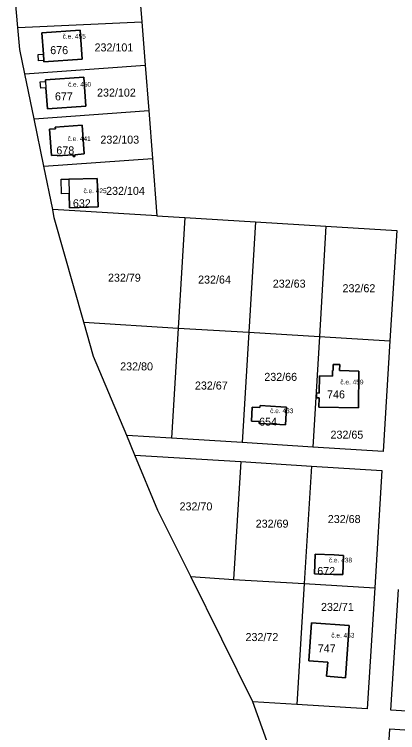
# Model space of a CAD drawing. Extents: x -887272 to -880188, y -1026687 to -1021896.
# Drawn here: x -882003.9 to -881922.6, y -1023755.1 to -1023602.5 of the extents above; entities that cross this region are included whole.
import ezdxf

# ---------------------------------------------------------------- set-up
doc = ezdxf.new("R2010")
doc.units = 0
for name, color, linetype in [('Definiční body', 7, 'Continuous'), ('Hranice parcel', 7, 'Continuous'), ('Parcelní čísla', 7, 'Continuous'), ('Polygon budovy', 7, 'Continuous'), ('Vnitřní kresba', 7, 'Continuous')]:
    doc.layers.add(name, color=color, linetype=linetype)

msp = doc.modelspace()

# ---------------------------------------------------------------- linework, layer by layer
at = {"layer": 'Hranice parcel'}
for p, q in [((-881977.56, -1023595.07), (-881976.82, -1023604.15)), ((-882003.11, -1023605.34), (-882003.86, -1023596.94)), ((-882003.11, -1023605.34), (-881976.82, -1023604.15)), ((-881976.82, -1023604.15), (-881976.12, -1023613.34)), ((-882001.64, -1023615.16), (-881976.12, -1023613.34)), ((-881976.12, -1023613.34), (-881975.38, -1023622.97)), ((-881999.69, -1023624.69), (-882001.64, -1023615.16)), ((-881999.69, -1023624.69), (-881975.38, -1023622.97)), ((-881975.38, -1023622.97), (-881974.6, -1023633.13)), ((-881997.63, -1023634.76), (-881999.69, -1023624.69)), ((-881997.63, -1023634.76), (-881974.6, -1023633.13)), ((-881974.6, -1023633.13), (-881973.66, -1023645.33)), ((-881995.74, -1023643.96), (-881997.63, -1023634.76)), ((-881973.66, -1023645.33), (-881995.74, -1023643.96)), ((-881973.66, -1023645.33), (-881967.74, -1023645.7)), ((-881967.74, -1023645.7), (-881969.15, -1023669.15)), ((-881967.74, -1023645.7), (-881952.7, -1023646.62)), ((-881952.7, -1023646.62), (-881954.14, -1023670.06)), ((-881952.7, -1023646.62), (-881937.78, -1023647.52)), ((-881937.78, -1023647.52), (-881939.18, -1023670.97)), ((-881989.11, -1023667.93), (-881969.15, -1023669.15)), ((-881969.15, -1023669.15), (-881970.55, -1023692.51)), ((-881969.15, -1023669.15), (-881954.14, -1023670.06)), ((-881954.14, -1023670.06), (-881955.58, -1023693.49)), ((-881954.14, -1023670.06), (-881939.18, -1023670.97)), ((-881939.18, -1023670.97), (-881940.59, -1023694.43)), ((-881939.18, -1023670.97), (-881924.21, -1023671.89)), ((-881970.55, -1023692.51), (-881980.01, -1023691.98)), ((-881978.29, -1023696.16), (-881980.01, -1023691.98)), ((-881955.58, -1023693.49), (-881970.55, -1023692.51)), ((-881940.59, -1023694.43), (-881955.58, -1023693.49)), ((-881978.29, -1023696.16), (-881955.81, -1023697.47)), ((-881955.81, -1023697.47), (-881957.38, -1023722.54)), ((-881955.81, -1023697.47), (-881940.88, -1023698.48)), ((-881940.88, -1023698.48), (-881942.4, -1023723.43)), ((-881953.3, -1023748.53), (-881966.43, -1023721.93)), ((-881966.43, -1023721.93), (-881957.38, -1023722.54)), ((-881957.38, -1023722.54), (-881942.4, -1023723.43)), ((-881942.4, -1023723.43), (-881943.98, -1023749.08)), ((-881942.4, -1023723.43), (-881927.45, -1023724.33)), ((-881943.98, -1023749.08), (-881953.3, -1023748.53))]:
    msp.add_line(p, q, dxfattribs=at)
for points in [[(-882001.64, -1023615.16), (-882002.7, -1023610), (-882003.11, -1023605.34)], [(-881997.61, -1023612.63), (-881997.63, -1023612.33), (-881998.72, -1023612.41), (-881998.82, -1023611.06), (-881997.72, -1023610.98), (-881998.04, -1023606.49), (-881989.91, -1023605.92), (-881989.47, -1023612.05), (-881997.61, -1023612.63)], [(-881997.26, -1023616.79), (-881997.28, -1023616.44), (-881989.15, -1023615.89), (-881988.74, -1023622.03), (-881996.87, -1023622.57), (-881997.17, -1023618.13), (-881998.27, -1023618.21), (-881998.36, -1023616.86), (-881997.26, -1023616.79)], [(-881995.19, -1023626.47), (-881989.49, -1023626.05), (-881989.05, -1023632.19), (-881991.04, -1023632.34), (-881991.01, -1023632.69), (-881991.36, -1023632.71), (-881991.38, -1023632.36), (-881994.77, -1023632.61), (-881994.78, -1023632.43), (-881995.99, -1023632.52), (-881996.4, -1023626.95), (-881995.16, -1023626.87), (-881995.19, -1023626.47)], [(-881992.27, -1023640.59), (-881993.86, -1023640.63), (-881993.94, -1023637.57), (-881992.34, -1023637.53), (-881986.28, -1023637.37), (-881986.12, -1023643.44), (-881992.19, -1023643.6), (-881992.27, -1023640.59)], [(-881989.11, -1023667.93), (-881995.4, -1023645.73), (-881995.74, -1023643.96)], [(-881937.78, -1023647.52), (-881922.75, -1023648.47), (-881924.21, -1023671.89)], [(-881980.01, -1023691.98), (-881987.07, -1023675.17), (-881989.11, -1023667.93)], [(-881924.21, -1023671.89), (-881925.66, -1023695.35), (-881940.59, -1023694.43)], [(-881939.24, -1023683.95), (-881939.79, -1023683.94), (-881939.77, -1023682.94), (-881939.22, -1023682.95), (-881939.14, -1023679.32), (-881936.43, -1023679.37), (-881936.4, -1023678.17), (-881936.28, -1023678.17), (-881936.26, -1023676.89), (-881934.86, -1023676.9), (-881934.88, -1023678.2), (-881930.78, -1023678.28), (-881930.87, -1023686.11), (-881939.29, -1023685.93), (-881939.24, -1023683.95)], [(-881951.79, -1023686.06), (-881951.77, -1023685.63), (-881947.36, -1023685.86), (-881946.14, -1023685.93), (-881946.34, -1023689.71), (-881947.54, -1023689.65), (-881951.97, -1023689.42), (-881951.94, -1023688.99), (-881953.61, -1023688.9), (-881953.46, -1023685.97), (-881951.79, -1023686.06)], [(-881966.43, -1023721.93), (-881973.45, -1023707.87), (-881978.29, -1023696.16)], [(-881940.88, -1023698.48), (-881925.91, -1023699.39), (-881927.45, -1023724.33)], [(-881936.17, -1023721.5), (-881940.21, -1023721.38), (-881940.08, -1023717.19), (-881936.02, -1023717.3), (-881934.08, -1023717.43), (-881934.2, -1023721.52), (-881936.17, -1023721.5)], [(-881927.45, -1023724.33), (-881929.02, -1023750.02), (-881943.98, -1023749.08)], [(-881909.11, -1023751.24), (-881924.05, -1023750.31), (-881922.43, -1023724.66)], [(-881933.43, -1023740.38), (-881933.65, -1023743.41), (-881937.69, -1023743.11), (-881937.41, -1023740.1), (-881941.43, -1023739.83), (-881940.88, -1023731.79), (-881932.84, -1023732.34), (-881933.43, -1023740.38)], [(-881934.53, -1023818.08), (-881937.73, -1023791.96), (-881953.3, -1023748.53)], [(-881925.8, -1023779.26), (-881924.27, -1023754.29), (-881909.32, -1023755.23)]]:
    msp.add_lwpolyline(points, dxfattribs=at)
at = {"layer": 'Polygon budovy'}
for points in [[(-881989.91, -1023605.92), (-881998.04, -1023606.49), (-881997.72, -1023610.98), (-881997.63, -1023612.33), (-881997.61, -1023612.63), (-881989.47, -1023612.05)], [(-881996.87, -1023622.57), (-881988.74, -1023622.03), (-881989.15, -1023615.89), (-881997.28, -1023616.44), (-881997.26, -1023616.79), (-881997.17, -1023618.13)], [(-881991.38, -1023632.36), (-881991.36, -1023632.71), (-881991.01, -1023632.69), (-881991.04, -1023632.34), (-881989.05, -1023632.19), (-881989.49, -1023626.05), (-881995.19, -1023626.47), (-881995.16, -1023626.87), (-881996.4, -1023626.95), (-881995.99, -1023632.52), (-881994.78, -1023632.43), (-881994.77, -1023632.61)], [(-881992.19, -1023643.6), (-881986.12, -1023643.44), (-881986.28, -1023637.37), (-881992.34, -1023637.53), (-881992.27, -1023640.59)], [(-881936.43, -1023679.37), (-881939.14, -1023679.32), (-881939.22, -1023682.95), (-881939.77, -1023682.94), (-881939.79, -1023683.94), (-881939.24, -1023683.95), (-881939.29, -1023685.93), (-881930.87, -1023686.11), (-881930.78, -1023678.28), (-881934.88, -1023678.2), (-881934.86, -1023676.9), (-881936.26, -1023676.89), (-881936.28, -1023678.17), (-881936.4, -1023678.17)], [(-881951.77, -1023685.63), (-881951.79, -1023686.06), (-881953.46, -1023685.97), (-881953.61, -1023688.9), (-881951.94, -1023688.99), (-881951.97, -1023689.42), (-881947.54, -1023689.65), (-881946.34, -1023689.71), (-881946.14, -1023685.93), (-881947.36, -1023685.86)], [(-881940.08, -1023717.19), (-881940.21, -1023721.38), (-881936.17, -1023721.5), (-881934.2, -1023721.52), (-881934.08, -1023717.43), (-881936.02, -1023717.3)], [(-881941.43, -1023739.83), (-881937.41, -1023740.1), (-881937.69, -1023743.11), (-881933.65, -1023743.41), (-881933.43, -1023740.38), (-881932.84, -1023732.34), (-881940.88, -1023731.79)]]:
    msp.add_lwpolyline(points, close=True, dxfattribs=at)
at = {"layer": 'Vnitřní kresba'}
for p, q in [((-881997.63, -1023612.33), (-881997.72, -1023610.98)), ((-881997.26, -1023616.79), (-881997.17, -1023618.13)), ((-881992.34, -1023637.53), (-881992.27, -1023640.59))]:
    msp.add_line(p, q, dxfattribs=at)

# ---------------------------------------------------------------- texts
at = {"layer": 'Definiční body'}
for s, p in [('č.e. 455', (-881993.63, -1023607.69)), ('č.e. 450', (-881992.5, -1023617.9)), ('č.e. 441', (-881992.58, -1023629.43)), ('č.e. 425', (-881989.2, -1023640.51)), ('č.e. 459', (-881934.73, -1023681.12)), ('č.e. 433', (-881949.62, -1023687.23)), ('č.e. 438', (-881937.17, -1023718.93)), ('č.e. 463', (-881936.66, -1023734.89))]:
    msp.add_text(s, height=1, dxfattribs=at).set_placement(p)
at = {"layer": 'Parcelní čísla'}
for s, p in [('232/101', (-881986.86, -1023610.41)), ('676', (-881996.26, -1023610.99)), ('677', (-881995.26, -1023620.8)), ('232/102', (-881986.33, -1023620)), ('232/103', (-881985.62, -1023629.99)), ('678', (-881994.96, -1023632.28)), ('232/104', (-881984.41, -1023640.87)), ('632', (-881991.45, -1023643.51)), ('232/79', (-881984.01, -1023659.31)), ('232/64', (-881964.9, -1023659.71)), ('232/63', (-881949.06, -1023660.57)), ('232/62', (-881934.27, -1023661.55)), ('232/80', (-881981.42, -1023678.15)), ('232/66', (-881950.86, -1023680.37)), ('232/67', (-881965.57, -1023682.21)), ('746', (-881937.55, -1023684.1)), ('654', (-881951.96, -1023689.89)), ('232/65', (-881936.82, -1023692.65)), ('232/70', (-881968.83, -1023707.88)), ('232/68', (-881937.4, -1023710.57)), ('232/69', (-881952.69, -1023711.55)), ('672', (-881939.63, -1023721.61)), ('232/71', (-881938.84, -1023729.23)), ('232/72', (-881954.84, -1023735.63)), ('747', (-881939.52, -1023738.05))]:
    msp.add_text(s, height=1.7, dxfattribs=at).set_placement(p)

doc.saveas('drawing.dxf')
